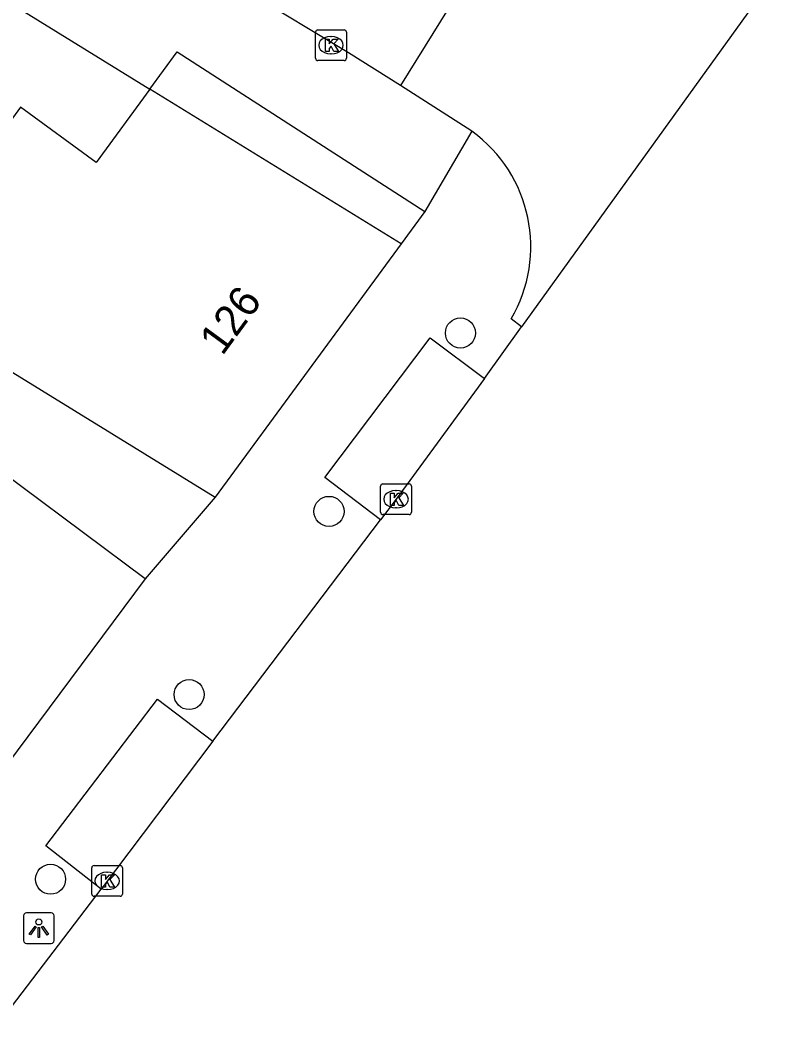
# Model space of a CAD drawing. Extents: x 160107 to 160928, y 382056 to 382918.
# Drawn here: x 160660.45 to 160685.14, y 382424.55 to 382457.11 of the extents above; entities that cross this region are included whole.
import ezdxf

# ---------------------------------------------------------------- set-up
doc = ezdxf.new("R2010")
doc.units = 0
for name, color, linetype in [('IMGEO_Boom', 7, 'Continuous'), ('IMGEO_Kolk', 7, 'Continuous'), ('IMGEO_Lichtpunt', 7, 'Continuous'), ('IMGEO_Pand', 7, 'Continuous'), ('IMGEO_Pand_nummerreeks', 7, 'Continuous'), ('IMGEO_Rijbaan_lokaal_gesloten', 7, 'Continuous'), ('IMGEO_Rijbaan_lokaal_open', 7, 'Continuous'), ('IMGEO_Voetpad_open', 7, 'Continuous')]:
    doc.layers.add(name, color=color, linetype=linetype)

msp = doc.modelspace()

# ---------------------------------------------------------------- linework, layer by layer
at = {"layer": 'IMGEO_Boom'}
for centre in [(160674.775, 382446.929), (160670.501, 382441.128), (160665.952, 382435.17), (160661.445, 382429.165)]:
    msp.add_circle(centre, 0.489, dxfattribs=at)
at = {"layer": 'IMGEO_Kolk'}
for p, q in [((160670.065, 382455.862), (160670.065, 382456.714)), ((160670.14, 382456.788), (160670.992, 382456.788)), ((160671.066, 382456.714), (160671.066, 382455.862)), ((160670.553, 382456.568), (160670.578, 382456.568)), ((160670.576, 382456.008), (160670.551, 382456.008)), ((160670.992, 382455.788), (160670.14, 382455.788)), ((160672.18, 382441.098), (160672.18, 382441.95)), ((160672.255, 382442.024), (160673.107, 382442.024)), ((160673.181, 382441.95), (160673.181, 382441.098)), ((160672.668, 382441.804), (160672.693, 382441.804)), ((160673.107, 382441.024), (160672.255, 382441.024)), ((160672.691, 382441.244), (160672.666, 382441.244)), ((160662.859, 382429.61), (160663.711, 382429.61)), ((160662.784, 382428.684), (160662.784, 382429.536)), ((160663.272, 382429.39), (160663.297, 382429.39)), ((160663.785, 382429.536), (160663.785, 382428.684)), ((160663.711, 382428.61), (160662.859, 382428.61)), ((160663.295, 382428.83), (160663.27, 382428.83))]:
    msp.add_line(p, q, dxfattribs=at)
for points in [[(160670.065, 382455.862), (160670.065, 382456.714)], [(160670.14, 382456.788), (160670.992, 382456.788)], [(160671.066, 382456.714), (160671.066, 382455.862)], [(160670.386, 382456.488), (160670.509, 382456.488), (160670.509, 382456.337), (160670.639, 382456.488), (160670.803, 382456.488), (160670.657, 382456.337), (160670.81, 382456.088), (160670.658, 382456.088), (160670.573, 382456.252), (160670.509, 382456.185), (160670.509, 382456.088), (160670.386, 382456.088), (160670.386, 382456.488)], [(160670.992, 382455.788), (160670.14, 382455.788)], [(160672.18, 382441.098), (160672.18, 382441.95)], [(160672.255, 382442.024), (160673.107, 382442.024)], [(160673.181, 382441.95), (160673.181, 382441.098)], [(160672.501, 382441.724), (160672.624, 382441.724), (160672.624, 382441.573), (160672.754, 382441.724), (160672.918, 382441.724), (160672.772, 382441.573), (160672.925, 382441.324), (160672.773, 382441.324), (160672.688, 382441.488), (160672.624, 382441.421), (160672.624, 382441.324), (160672.501, 382441.324), (160672.501, 382441.724)], [(160673.107, 382441.024), (160672.255, 382441.024)], [(160662.859, 382429.61), (160663.711, 382429.61)], [(160662.784, 382428.684), (160662.784, 382429.536)], [(160663.105, 382429.31), (160663.228, 382429.31), (160663.228, 382429.159), (160663.358, 382429.31), (160663.522, 382429.31), (160663.376, 382429.159), (160663.529, 382428.91), (160663.377, 382428.91), (160663.292, 382429.074), (160663.228, 382429.007), (160663.228, 382428.91), (160663.105, 382428.91), (160663.105, 382429.31)], [(160663.785, 382429.536), (160663.785, 382428.684)], [(160663.711, 382428.61), (160662.859, 382428.61)]]:
    msp.add_lwpolyline(points, dxfattribs=at)
for centre, start, end in [((160670.142, 382456.712), 91.552, 178.448), ((160670.142, 382456.712), 91.552, 178.448), ((160670.99, 382456.712), 1.552, 88.448), ((160670.99, 382456.712), 1.552, 88.448), ((160670.142, 382455.864), 181.552, 268.448), ((160670.142, 382455.864), 181.552, 268.448), ((160670.99, 382455.864), 271.552, 358.448), ((160670.99, 382455.864), 271.552, 358.448), ((160672.257, 382441.948), 91.552, 178.448), ((160672.257, 382441.948), 91.552, 178.448), ((160673.105, 382441.948), 1.552, 88.448), ((160673.105, 382441.948), 1.552, 88.448), ((160672.257, 382441.1), 181.552, 268.448), ((160672.257, 382441.1), 181.552, 268.448), ((160673.105, 382441.1), 271.552, 358.448), ((160673.105, 382441.1), 271.552, 358.448), ((160662.861, 382429.534), 91.552, 178.448), ((160662.861, 382429.534), 91.552, 178.448), ((160663.709, 382429.534), 1.552, 88.448), ((160663.709, 382429.534), 1.552, 88.448), ((160662.861, 382428.686), 181.552, 268.448), ((160662.861, 382428.686), 181.552, 268.448), ((160663.709, 382428.686), 271.552, 358.448), ((160663.709, 382428.686), 271.552, 358.448)]:
    msp.add_arc(centre, 0.0765, start, end, dxfattribs=at)
for centre, major_axis, ratio, start_param, end_param in [((160670.552, 382456.288), (-0.387, 0.002), 0.722429, 4.712389, 7.853982), ((160670.577, 382456.288), (-0.39, 0.002), 0.717154, 1.570796, 4.712389), ((160672.667, 382441.524), (-0.387, 0.002), 0.722429, 4.712389, 7.853982), ((160672.692, 382441.524), (-0.39, 0.002), 0.717154, 1.570796, 4.712389), ((160663.271, 382429.11), (-0.387, 0.002), 0.722429, 4.712389, 7.853982), ((160663.296, 382429.11), (-0.39, 0.002), 0.717154, 1.570796, 4.712389)]:
    msp.add_ellipse(centre, major_axis=major_axis, ratio=ratio, start_param=start_param, end_param=end_param, dxfattribs=at)
at = {"layer": 'IMGEO_Lichtpunt'}
for p, q in [((160660.565, 382427.978), (160660.565, 382427.171)), ((160660.565, 382427.978), (160660.565, 382427.171)), ((160661.467, 382428.073), (160660.659, 382428.073)), ((160661.467, 382428.073), (160660.659, 382428.073)), ((160661.561, 382427.171), (160661.561, 382427.978)), ((160661.561, 382427.171), (160661.561, 382427.978)), ((160660.659, 382427.077), (160661.467, 382427.077)), ((160660.659, 382427.077), (160661.467, 382427.077))]:
    msp.add_line(p, q, dxfattribs=at)
for points in [[(160660.939, 382427.642), (160660.978, 382427.614), (160660.79, 382427.352), (160660.752, 382427.379), (160660.939, 382427.642)], [(160661.151, 382427.614), (160661.189, 382427.641), (160661.376, 382427.379), (160661.337, 382427.351), (160661.151, 382427.614)], [(160661.041, 382427.594), (160661.088, 382427.594), (160661.088, 382427.272), (160661.041, 382427.272), (160661.041, 382427.594)]]:
    msp.add_lwpolyline(points, dxfattribs=at)
msp.add_circle((160661.064, 382427.776), 0.0994, dxfattribs=at)
for centre, start, end in [((160660.659, 382427.978), 90, 180), ((160660.659, 382427.978), 90, 180), ((160661.467, 382427.978), 0, 90), ((160661.467, 382427.978), 0, 90), ((160660.659, 382427.171), 180, 270), ((160660.659, 382427.171), 180, 270), ((160661.467, 382427.171), 270, 0), ((160661.467, 382427.171), 270, 360)]:
    msp.add_arc(centre, 0.0946, start, end, dxfattribs=at)
at = {"layer": 'IMGEO_Pand'}
for points in [[(160664.677, 382454.86), (160662.926, 382452.473), (160660.47, 382454.274), (160659.015, 382452.289), (160646.208, 382460.179), (160646.451, 382460.573), (160642.506, 382463.004), (160640.309, 382464.367), (160640.037, 382463.924), (160637.426, 382459.686), (160637.554, 382459.607)], [(160645.131, 382454.939), (160666.802, 382441.589)], [(160672.844, 382449.829), (160664.677, 382454.86)], [(160672.844, 382449.829), (160666.802, 382441.589)], [(160664.522, 382438.938), (160660.514, 382441.927), (160657.392, 382444.254), (160655.259, 382441.394), (160652.682, 382443.316), (160649.596, 382439.179)], [(160664.522, 382438.938), (160659.305, 382431.941)]]:
    msp.add_lwpolyline(points, dxfattribs=at)
at = {"layer": 'IMGEO_Rijbaan_lokaal_gesloten'}
for points in [[(160675.554, 382445.444), (160676.766, 382447.127)], [(160675.554, 382445.444), (160672.681, 382441.524), (160672.173, 382440.853)], [(160666.725, 382433.654), (160672.173, 382440.853)], [(160666.725, 382433.654), (160663.086, 382428.847)], [(160659.831, 382424.555), (160663.086, 382428.847)]]:
    msp.add_lwpolyline(points, dxfattribs=at)
at = {"layer": 'IMGEO_Rijbaan_lokaal_open'}
for points in [[(160675.977, 382460.059), (160672.822, 382454.976)], [(160672.822, 382454.976), (160671.139, 382456.041), (160667.848, 382458.021), (160666.192, 382459.055)], [(160685.136, 382458.755), (160676.766, 382447.127)], [(160675.151, 382453.489), (160672.822, 382454.976)], [(160676.766, 382447.127), (160676.422, 382447.388)]]:
    msp.add_lwpolyline(points, dxfattribs=at)
msp.add_arc((160672.43, 382449.739), 4.633, 329.504, 54.0318, dxfattribs=at)
at = {"layer": 'IMGEO_Voetpad_open'}
for points in [[(160652.296, 382462.502), (160664.677, 382454.86)], [(160664.677, 382454.86), (160665.564, 382456.069), (160673.613, 382450.877)], [(160675.151, 382453.489), (160673.613, 382450.877)], [(160673.613, 382450.877), (160672.844, 382449.829)], [(160672.173, 382440.853), (160670.36, 382442.229), (160673.792, 382446.774), (160675.554, 382445.444)], [(160666.802, 382441.589), (160664.522, 382438.938)], [(160663.086, 382428.847), (160661.287, 382430.247), (160664.925, 382435.025), (160666.725, 382433.654)]]:
    msp.add_lwpolyline(points, dxfattribs=at)

# ---------------------------------------------------------------- texts
at = {"layer": 'IMGEO_Pand_nummerreeks'}
msp.add_text('126', height=1, rotation=53.7492, dxfattribs=at).set_placement((160667.03, 382446.162))

doc.saveas('drawing.dxf')
